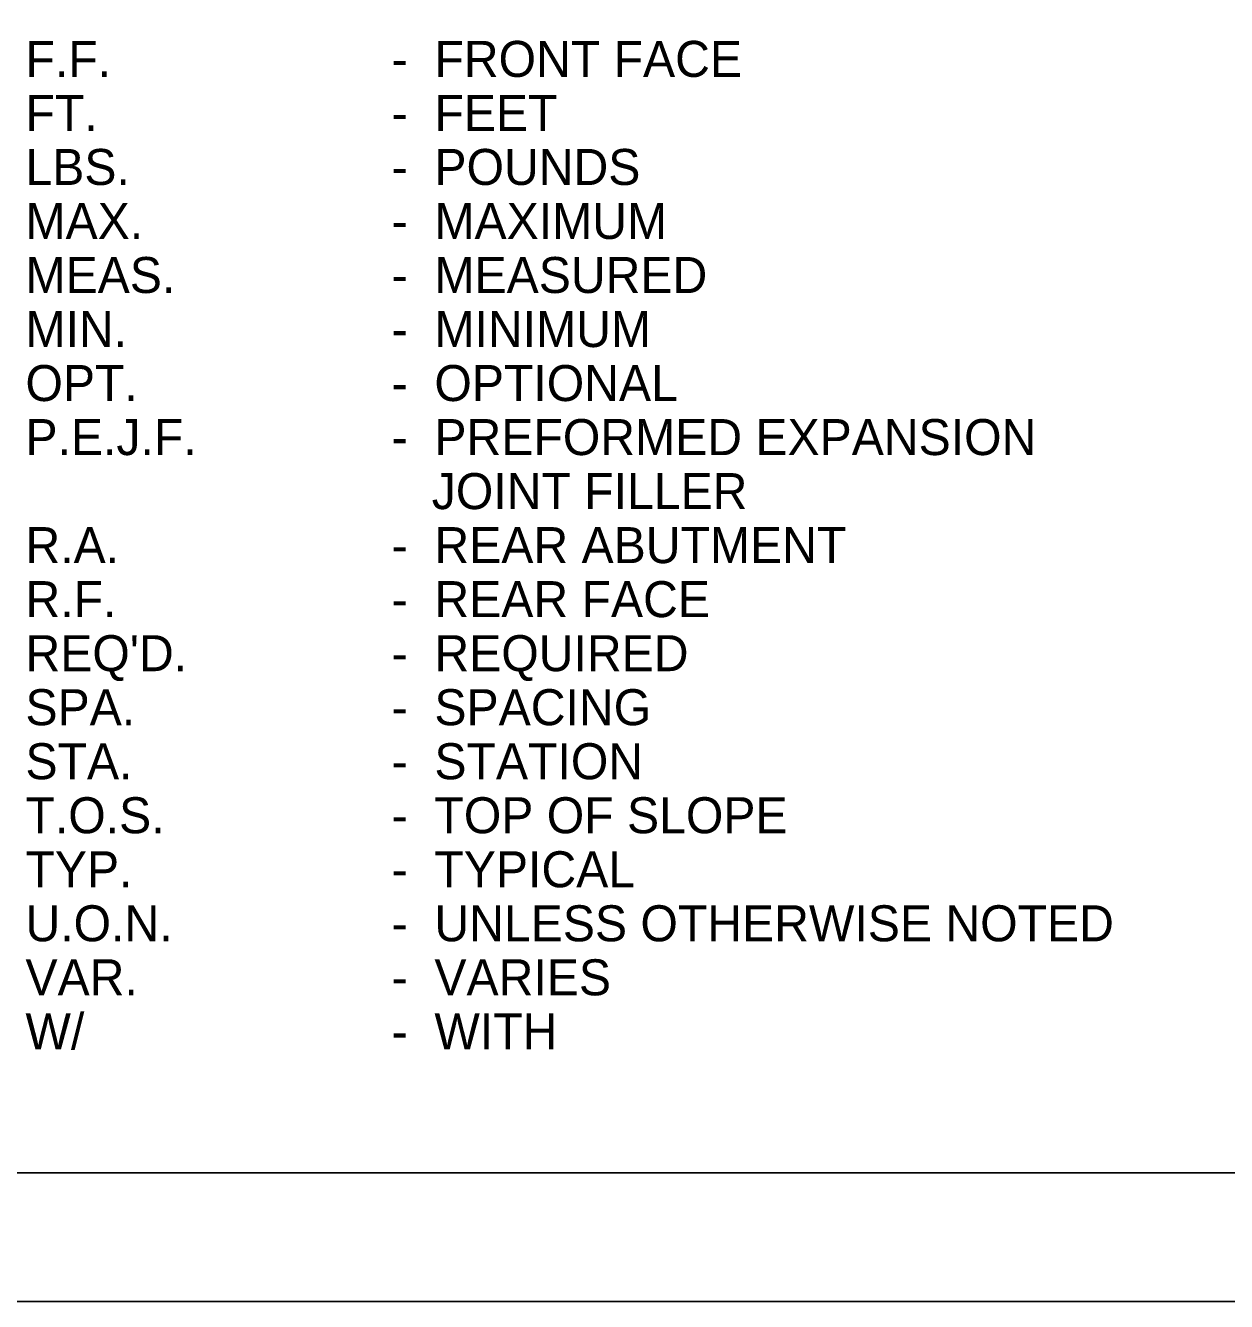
# Model space of a CAD drawing. Extents: x 0 to 34, y 0 to 22.
# Drawn here: x 24.66 to 29.33, y 0 to 4.96 of the extents above; entities that cross this region are included whole.
import ezdxf

# ---------------------------------------------------------------- set-up
doc = ezdxf.new("R2010")
doc.units = 0
for name, color, linetype in [('BR_P_Gen_Text', 7, 'Continuous'), ('SH_Border', 7, 'Continuous'), ('SH_Cut_Line', 7, 'Continuous')]:
    doc.layers.add(name, color=color, linetype=linetype)

msp = doc.modelspace()

# ---------------------------------------------------------------- linework, layer by layer
at = {"layer": 'SH_Border'}
msp.add_lwpolyline([(1.5, 21.5), (33.5, 21.5), (33.5, 0.5), (1.5, 0.5)], close=True, dxfattribs=at)
at = {"layer": 'SH_Cut_Line'}
msp.add_lwpolyline([(0, 0), (34, 0), (34, 22), (0, 22)], close=True, dxfattribs=at)

# ---------------------------------------------------------------- texts
at = {"layer": 'BR_P_Gen_Text'}
for s, p in [('F.F.', (24.66, 4.76)), ('-  FRONT FACE', (26.0838, 4.76)), ('FT.', (24.66, 4.55)), ('-  FEET', (26.0838, 4.55)), ('LBS.', (24.66, 4.34)), ('-  POUNDS', (26.0838, 4.34)), ('MAX.', (24.66, 4.13)), ('-  MAXIMUM', (26.0838, 4.13)), ('MEAS.', (24.66, 3.92)), ('-  MEASURED', (26.0838, 3.92)), ('MIN.', (24.66, 3.71)), ('-  MINIMUM', (26.0838, 3.71)), ('OPT.', (24.66, 3.5)), ('-  OPTIONAL', (26.0838, 3.5)), ('P.E.J.F.', (24.66, 3.29)), ('-  PREFORMED EXPANSION', (26.0838, 3.29)), ('   JOINT FILLER', (26.0838, 3.08)), ('R.A.', (24.66, 2.87)), ('-  REAR ABUTMENT', (26.0838, 2.87)), ('R.F.', (24.66, 2.66)), ('-  REAR FACE', (26.0838, 2.66)), ("REQ'D.", (24.66, 2.45)), ('-  REQUIRED', (26.0838, 2.45)), ('SPA.', (24.66, 2.24)), ('-  SPACING', (26.0838, 2.24)), ('STA. ', (24.66, 2.03)), ('-  STATION', (26.0838, 2.03)), ('T.O.S.', (24.66, 1.82)), ('-  TOP OF SLOPE', (26.0838, 1.82)), ('TYP.', (24.66, 1.61)), ('-  TYPICAL', (26.0838, 1.61)), ('U.O.N.', (24.66, 1.4)), ('-  UNLESS OTHERWISE NOTED', (26.0838, 1.4)), ('VAR.', (24.66, 1.19)), ('-  VARIES', (26.0838, 1.19)), ('W/', (24.66, 0.98)), ('-  WITH', (26.0838, 0.98))]:
    msp.add_text(s, height=0.14, dxfattribs=at).set_placement(p)

doc.saveas('drawing.dxf')
